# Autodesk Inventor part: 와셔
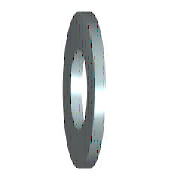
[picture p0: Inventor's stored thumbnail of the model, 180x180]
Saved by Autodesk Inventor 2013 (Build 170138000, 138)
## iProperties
Created: 2012-02
Part Number: 와셔
Material: 강철, 연강
Description: 평면 와셔
Document SubType Name: Modeling
Standard: KS B 1326
Designer: mduedu
Standards Organization: KS
Language: ko-KR
Size Designation: 8x15.5
Categories: <MemberInstance><Categories><Category DisplayName="조임쇠" InternalName="e4da775c-781d-43d5-af7c-5136215cf5a6" Mnemonic="FSTN"><Category DisplayName="와셔" InternalN
Density: 1 g/cm^3
IsCustomPart: 1
Author: mduedu
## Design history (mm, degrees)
sketch "스케치"
  geometry: C1 r 7.75 at (0, 0); C2 r 4.2 at (0, 0); 1 further point
  constraints: 2 centre point, 2 coincident
  dimensions: "d0" = 8.4 diameter of C2 (= SD1); "d1" = 15.5 diameter of C1 (= SD2)
extrude "본체" new body sketch "스케치" distance "d2" = 1.6 (= SD); taper "d3" = 0 deg
workaxis "Work Axis1"
workplane "Work Plane1"
body "Solid1"
other parameters: "SD1" = 8.4 [user parameter; used in 1 equation term], "SD2" = 15.5 [user parameter; used in 1 equation term], "SD" = 1.6 [user parameter; used in 1 equation term], "d4" = 0, "d5" = 0, "d6" = 0, "d7" = 0, "NND" = 8 [user parameter]
